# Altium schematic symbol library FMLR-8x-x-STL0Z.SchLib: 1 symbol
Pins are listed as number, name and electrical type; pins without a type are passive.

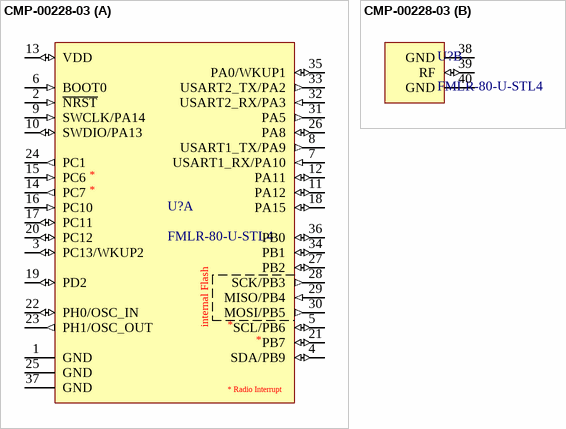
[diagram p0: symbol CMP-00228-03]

## CMP-00228-03
designator U?, comment FMLR-80-U-STL4
FMLR LoRa Module with SX1280 Transceiver and STM32L4 MCU; Manufacturer: Miromico
footprint FMLR-80-U-STL4-Footprint-1
part A pins: 1 GND (power), 2 ~{NRST} (in), 3 PC13/WKUP2 (io), 4 SDA/PB9 (io), 5 SCL/PB6 (io), 6 BOOT0 (in), 7 USART1_RX/PA10 (in), 8 USART1_TX/PA9 (out), 9 SWCLK/PA14 (in), 10 SWDIO/PA13 (io), 11 PA12 (io), 12 PA11 (io), 13 VDD (io), 14 PC7 (out), 15 PC6 (in), 16 PC10 (in), 17 PC11 (io), 18 PA15 (io), 19 PD2 (io), 20 PC12 (io), 21 PB7 (io), 22 PH0/OSC_IN (io), 23 PH1/OSC_OUT (out), 24 PC1 (out), 25 GND (power), 26 PA8 (io), 27 PB2 (io), 28 SCK/PB3 (out), 29 MISO/PB4 (in), 30 MOSI/PB5 (out), 31 PA5 (out), 32 USART2_RX/PA3 (in), 33 USART2_TX/PA2 (out), 34 PB1 (io), 35 PA0/WKUP1 (io), 36 PB0 (io), 37 GND (power)
part B pins: 38 GND (power) "Serial Interface Data", 39 RF (io) "Serial Interface Data", 40 GND (power) "Serial Interface Data"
